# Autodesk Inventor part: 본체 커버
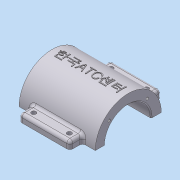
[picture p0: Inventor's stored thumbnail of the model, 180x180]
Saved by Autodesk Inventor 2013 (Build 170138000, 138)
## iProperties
Company: 한국ATC센터
Created: 2014-02
Part Number: 본체 커버
Document SubType Name: Modeling
Designer: KYOUNG IL JANG
Density: 2.71 g/cm^3
Mass: 199.244 g
Surface Area: 195.422 cm^2
Volume: 73.5218 cm^3
Material: 알루미늄-6061
Vendor: CBT Solutions
Author: KYOUNG IL JANG
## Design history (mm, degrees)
sketch "스케치1"
  geometry: L1 (-45, 40)-(45, 40); L2 (45, 40)-(45, -40); L3 (45, -40)-(-45, -40); L4 (-45, -40)-(-45, 40); 3 further points
  constraints: 8 end point, 2 midpoint, 2 parallel, 1 horizontal, 1 horizontal alignment, 1 perpendicular, 1 vertical alignment
  dimensions: "d0" = 90 distance of L2.end L3.end; "d1" = 80 distance of L1.end L2.end
extrude "돌출1" new body sketch "스케치1" distance "d2" = 10; taper "d3" = 0 deg
sketch "스케치2"
  geometry: L1 (40, 0)-(-40, 0) reference; C1 r 32.5 at (0, 80); 2 further points
  constraints: 1 centre point, 1 midpoint, 1 vertical alignment
  dimensions: "d4" = 65 diameter of C1; "d5" = 80 distance from line of C1.centre L1
extrude "돌출2" join sketch "스케치2" stored distance "d6" = 75; taper "d7" = 0 deg
sketch "스케치3"
  geometry: L1 (-7.5, -20)-(7.5, -20); L2 (7.5, 20)-(-7.5, 20); A1 r 20 centre (7.5, 0) between (7.5, -20) and (7.5, 20); A2 r 20 centre (-7.5, 0) between (-7.5, 20) and (-7.5, -20); 2 further points
  constraints: 4 end point, 4 point on circle, 4 tangent, 2 centre point, 1 horizontal, 1 horizontal alignment, 1 midpoint, 1 parallel, 1 vertical alignment
  dimensions: "d8" = 20 radius of A2; "d9" = 55 dimension on A1 A2
extrude "돌출3" join sketch "스케치3" stored distance "d10" = 75; taper "d11" = 0 deg
fillet "모깎기1" dims "d12" = 10
sketch "스케치4"
  geometry: L1 (-45, 0)-(-45, 10) reference; L2 (37.5, 47.5)-(-37.5, 47.5) reference; L3 (-45, 10)-(-27.513, 47.5); 1 further point
  constraints: 2 end point, 1 point on line
  dimensions: "d13" = 25 deg angle of L3 L1
sketch "스케치5"
  geometry: L1 (-40, 0)-(-40, 10) reference; L2 (-40, 10)-(-22.912, 56.95); 2 further points
  constraints: 2 end point, 2 other
  dimensions: "d14" = 20 deg angle of L2 L1
feature "리브1" dims "d15" = 1, "d16" = 6, "d17" = 0
feature "리브2" dims "d18" = 1, "d19" = 6, "d20" = 0
fillet "모깎기2" dims "d21" = 3
fillet "모깎기3" dims "d22" = 3
fillet "모깎기4" dims "d23" = 3
fillet "모깎기5" dims "d24" = 3
fillet "모깎기6" dims "d25" = 3
fillet "모깎기7" dims "d26" = 3
fillet "모깎기8" dims "d27" = 3
sketch "스케치6"
  geometry: A1 r 10 centre (35, -30) between (35, -40) and (45, -30) reference; 1 further point
hole "구멍1" sketch "스케치6" at (35, -30) diameter "d28" = 10; stored, may be unused: countersink angle "d32" = 90 deg, drill point angle "d34" = 118 deg; dims "d29" = 6, "d30" = 4, "d31" = 2, "d33" = 8
hole "구멍2" diameter "d37" = 45; stored, may be unused: countersink angle "d41" = 90 deg, drill point angle "d43" = 118 deg; dims "d35" = 10, "d36" = 10, "d38" = 6, "d39" = 4, "d40" = 2, "d42" = 8
sketch "스케치7"
  geometry: C1 r 22.5 at (0, 0) reference; 2 further points
  dimensions: "d44" = 135 deg dimension on C1.centre point (-18.738, 18.738) point (80, 0); "d45" = 26.5 distance of point (-18.738, 18.738) C1.centre
hole "구멍3" sketch "스케치7" at (-18.738, 18.738) diameter "d46" = 2.459; stored, may be unused: countersink angle "d50" = 90 deg, drill point angle "d52" = 118 deg; dims "d47" = 8, "d48" = 4, "d49" = 2, "d51" = 10
node "작업 평면1"
chamfer "모따기1" distance "d69" = 1; stored, may be unused: second distance "d70" = 2, angle "d71" = 45 deg
sketch "스케치9"
  geometry: L1 (-31.623, 87.5)-(-45, 87.5); L2 (-45, 87.5)-(-45, 72.5); L3 (-45, 72.5)-(-31.623, 72.5); A1 r 32.5 centre (0, 80) between (-31.623, 87.5) and (-31.623, 72.5) reference; 1 further point
  constraints: 6 end point, 2 parallel, 2 point on circle, 1 horizontal, 1 perpendicular
  dimensions: "d73" = 15 distance of L1.end L2.end; "d74" = 45 distance from line of A1.centre L2
extrude "돌출5" join sketch "스케치9" stored distance "d75" = 50; taper "d76" = 0 deg
fillet "모깎기10" dims "d77" = 3
fillet "모깎기11" dims "d78" = 3
sketch "스케치10"
  geometry: L1 (100.378, 66.389)-(0, 66.389); L2 (0, 66.389)-(0, -76.978); L3 (0, -76.978)-(100.378, -76.978); L4 (100.378, -76.978)-(100.378, 66.389); C1 r 32.5 at (0, 0) reference; 1 further point
  constraints: 8 end point, 2 parallel, 1 horizontal, 1 perpendicular, 1 point on line
extrude "돌출6" cut sketch "스케치10" stored distance "d79" = 10; taper "d80" = 0 deg
sketch "스케치11"
  geometry: C1 r 1.621 at (4.5, 4) reference; C2 r 1.621 at (39.5, 4) reference; 1 further point
hole "구멍5" sketch "스케치11" at (39.5, 4), (4.5, 4) diameter "d81" = 4.5; stored, may be unused: countersink angle "d85" = 90 deg, drill point angle "d87" = 118 deg; dims "d82" = 6, "d83" = 4, "d84" = 2, "d86" = 8
node "작업 평면2"
sketch "스케치12"
  geometry: 2 further points
  constraints: 1 coincident, 1 other
feature "엠보싱1" sketch "스케치12" dims "d8" = 20, "d9" = 55, "d88" = 0.5, "d89" = 0
node "솔리드1"
mirror "대칭1"
mirror "대칭2"
mirror "대칭3"
mirror "대칭4"
pattern_circular "원형 패턴1" dims angle "d54" = 360 deg
mirror "대칭5"
mirror "대칭6"
mirror "대칭7"
node "참조1"
node "참조2"
other parameters: "d56" = -117
